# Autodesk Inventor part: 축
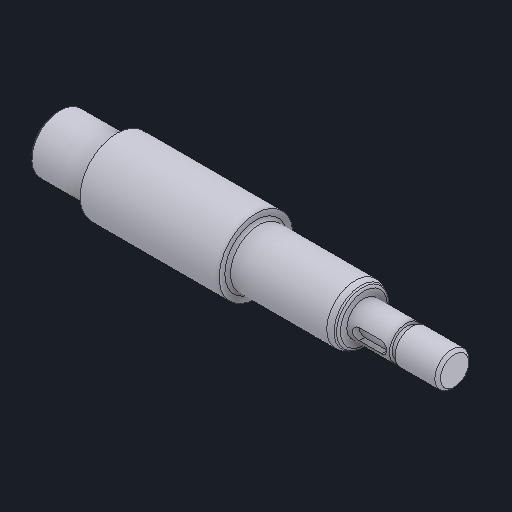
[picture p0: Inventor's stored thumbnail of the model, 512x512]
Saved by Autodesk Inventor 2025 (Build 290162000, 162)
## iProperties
Created: 2025-08
Part Number: 축
Material: 강철, 연강
Document SubType Name: Modeling
Designer: infra023
Density: 7.86 g/cm^3
Appearance: 기본값
Author: jhkim
Sending System: Autodesk Inventor 2026
Preprocessor: ST-DEVELOPER v20.1
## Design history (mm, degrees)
feature "솔리드2"
node "솔리드1"
